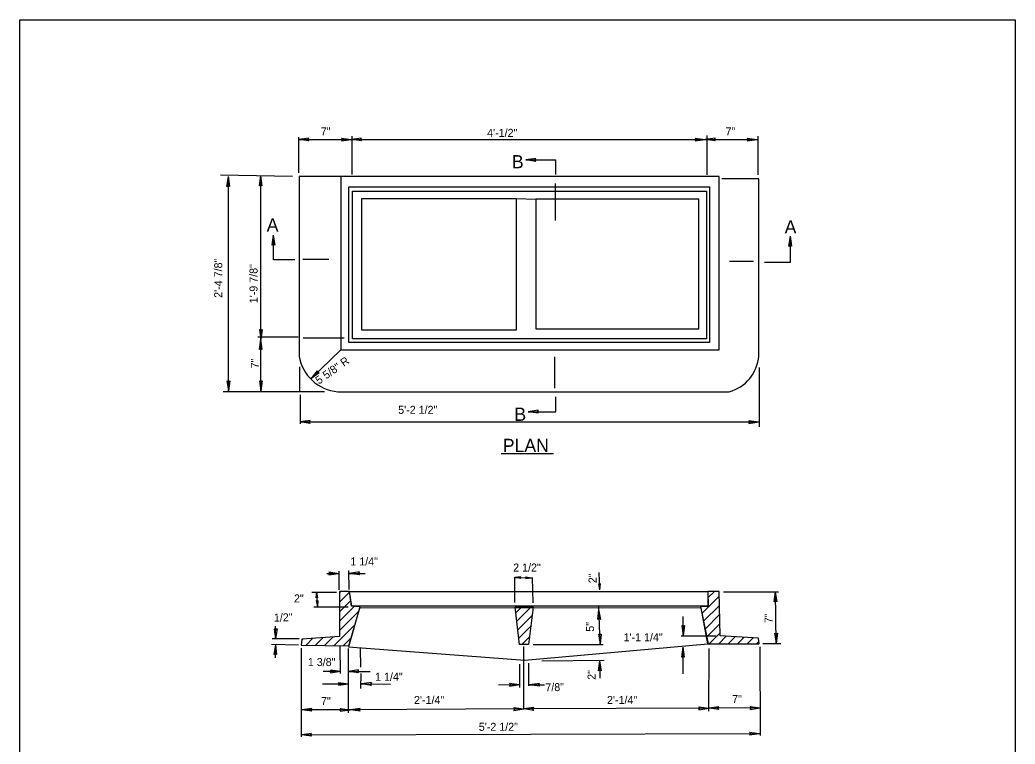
# Model space of a CAD drawing. Extents: x 0.7 to 8.1, y 0.4 to 10.6.
# Drawn here: x 0.66 to 8.12, y 5.19 to 10.63 of the extents above; entities that cross this region are included whole.
import ezdxf

# ---------------------------------------------------------------- set-up
doc = ezdxf.new("R2010")
doc.units = 0
for name, color, linetype in [('DETL-DIMS', 7, 'Continuous'), ('DETL-LINE', 7, 'Continuous'), ('DETL-NOTE', 7, 'Continuous'), ('DETL-TITL', 7, 'Continuous')]:
    doc.layers.add(name, color=color, linetype=linetype)

msp = doc.modelspace()

# ---------------------------------------------------------------- linework, layer by layer
at = {"layer": 'DETL-DIMS'}
for p, q in [((2.7543, 9.478), (2.7543, 9.7472)), ((2.8293, 9.7399), (2.7543, 9.729)), ((2.7543, 9.729), (3.1505, 9.729)), ((2.8293, 9.718), (2.7543, 9.729)), ((2.8293, 9.7399), (2.8199, 9.729)), ((2.8293, 9.718), (2.8199, 9.729)), ((3.0755, 9.7399), (3.1505, 9.729)), ((3.0755, 9.7399), (3.0849, 9.729)), ((3.0755, 9.718), (3.1505, 9.729)), ((3.0755, 9.718), (3.0849, 9.729)), ((3.2255, 9.7399), (3.1505, 9.729)), ((3.1505, 9.729), (5.8026, 9.729)), ((3.2255, 9.718), (3.1505, 9.729)), ((3.1541, 9.4671), (3.1541, 9.7544)), ((3.2255, 9.7399), (3.2161, 9.729)), ((3.2255, 9.718), (3.2161, 9.729)), ((5.7276, 9.718), (5.8027, 9.729)), ((5.7276, 9.718), (5.737, 9.729)), ((5.7277, 9.7399), (5.8027, 9.729)), ((5.7277, 9.7399), (5.737, 9.729)), ((5.8026, 9.729), (6.1916, 9.729)), ((5.8777, 9.7399), (5.8027, 9.729)), ((5.8777, 9.718), (5.8027, 9.729)), ((5.8172, 9.4636), (5.8172, 9.7582)), ((5.8777, 9.7399), (5.8683, 9.729)), ((5.8777, 9.718), (5.8683, 9.729)), ((6.1166, 9.7399), (6.1916, 9.729)), ((6.1166, 9.7399), (6.126, 9.729)), ((6.1166, 9.718), (6.1916, 9.729)), ((6.1166, 9.718), (6.126, 9.729)), ((6.1989, 9.4636), (6.1989, 9.7546)), ((4.5327, 9.587), (4.4576, 9.576)), ((4.5326, 9.5651), (4.4576, 9.576)), ((4.5327, 9.587), (4.5232, 9.576)), ((4.5326, 9.5651), (4.5232, 9.576)), ((2.7086, 9.4507), (2.1675, 9.4602)), ((2.2162, 9.3776), (2.2271, 9.4526)), ((2.2271, 7.8427), (2.2271, 9.4526)), ((2.238, 9.3776), (2.2271, 9.4526)), ((2.4597, 9.3812), (2.4706, 9.4562)), ((2.4706, 8.2282), (2.4706, 9.4562)), ((2.4816, 9.3812), (2.4706, 9.4562)), ((2.2162, 9.3776), (2.2271, 9.3869)), ((2.238, 9.3776), (2.2271, 9.3869)), ((2.4597, 9.3812), (2.4706, 9.3906)), ((2.4816, 9.3812), (2.4706, 9.3906)), ((4.6758, 9.3979), (4.6758, 9.1207)), ((2.5547, 8.9369), (2.5657, 9.0119)), ((2.5766, 8.9368), (2.5657, 9.0119)), ((6.4297, 8.9281), (6.4407, 9.0031)), ((6.4516, 8.9281), (6.4407, 9.0031)), ((2.5547, 8.9369), (2.5657, 8.9463)), ((2.5766, 8.9368), (2.5657, 8.9463)), ((6.4297, 8.9281), (6.4407, 8.9375)), ((6.4516, 8.9281), (6.4407, 8.9375)), ((2.9813, 8.8275), (2.7842, 8.8275)), ((5.9837, 8.8169), (6.1633, 8.8169)), ((2.4597, 8.3033), (2.4706, 8.2282)), ((2.4597, 8.3033), (2.4706, 8.2938)), ((2.4816, 8.3032), (2.4706, 8.2282)), ((2.4816, 8.3032), (2.4706, 8.2938)), ((2.7505, 8.2464), (2.4488, 8.2464)), ((2.4597, 8.1532), (2.4706, 8.2282)), ((2.4706, 7.8427), (2.4706, 8.2282)), ((2.4816, 8.1532), (2.4706, 8.2282)), ((3.0959, 8.2391), (2.7869, 8.2391)), ((2.4597, 8.1532), (2.4706, 8.1626)), ((2.4816, 8.1532), (2.4706, 8.1626)), ((3.0702, 8.1505), (2.8461, 7.9346)), ((4.6751, 7.8641), (4.6751, 8.0976)), ((2.7614, 8.0246), (2.7614, 7.8427)), ((2.8925, 7.9945), (2.8461, 7.9346)), ((2.8925, 7.9945), (2.8933, 7.9801)), ((6.2089, 7.5736), (6.2089, 8.0173)), ((2.2162, 7.9177), (2.2271, 7.8427)), ((2.2162, 7.9177), (2.2271, 7.9083)), ((2.238, 7.9177), (2.2271, 7.8427)), ((2.238, 7.9177), (2.2271, 7.9083)), ((2.4597, 7.9177), (2.4706, 7.8427)), ((2.4597, 7.9177), (2.4706, 7.9083)), ((2.4816, 7.9177), (2.4706, 7.8427)), ((2.4816, 7.9177), (2.4706, 7.9083)), ((2.9077, 7.9787), (2.8461, 7.9346)), ((2.9077, 7.9787), (2.8933, 7.9801)), ((2.9468, 7.8354), (2.1871, 7.8354)), ((2.7651, 7.8136), (2.7651, 7.5954)), ((4.5502, 7.698), (4.4752, 7.687)), ((4.5502, 7.6761), (4.4752, 7.687)), ((4.5502, 7.698), (4.5408, 7.687)), ((4.5502, 7.6761), (4.5408, 7.687)), ((2.8393, 7.6209), (2.7643, 7.61)), ((2.8393, 7.6209), (2.8299, 7.61)), ((6.128, 7.6209), (6.203, 7.61)), ((6.128, 7.6209), (6.1374, 7.61)), ((2.7643, 7.61), (6.203, 7.61)), ((2.8393, 7.599), (2.7643, 7.61)), ((2.8393, 7.599), (2.8299, 7.61)), ((6.128, 7.599), (6.203, 7.61)), ((6.128, 7.599), (6.1374, 7.61)), ((3.1336, 6.3524), (3.1291, 6.4947)), ((2.9659, 6.4737), (3.0558, 6.4737)), ((2.9808, 6.4847), (3.0558, 6.4737)), ((2.9808, 6.4847), (2.9901, 6.4737)), ((2.9808, 6.4628), (3.0558, 6.4737)), ((2.9808, 6.4628), (2.9901, 6.4737)), ((3.0588, 6.3509), (3.0573, 6.4902)), ((3.2101, 6.4847), (3.1351, 6.4737)), ((3.1351, 6.4737), (3.2519, 6.4737)), ((3.2101, 6.4628), (3.1351, 6.4737)), ((3.2101, 6.4847), (3.2008, 6.4737)), ((3.2101, 6.4628), (3.2008, 6.4737)), ((4.3757, 6.2563), (4.3735, 6.4448)), ((4.4208, 6.4483), (4.3757, 6.4426)), ((4.3757, 6.4426), (4.4998, 6.4403)), ((4.4206, 6.4352), (4.3757, 6.4426)), ((4.4208, 6.4483), (4.4151, 6.4418)), ((4.4206, 6.4352), (4.4151, 6.4418)), ((4.4547, 6.4346), (4.4605, 6.441)), ((4.4547, 6.4346), (4.4998, 6.4403)), ((4.455, 6.4477), (4.4998, 6.4403)), ((4.455, 6.4477), (4.4605, 6.441)), ((4.5109, 6.2541), (4.5065, 6.4426)), ((5.0052, 6.4803), (5.0096, 6.3516)), ((5.0015, 6.3964), (5.0097, 6.3516)), ((5.0015, 6.3964), (5.0083, 6.391)), ((5.0147, 6.3968), (5.0083, 6.391)), ((5.0147, 6.3968), (5.0097, 6.3516)), ((2.8536, 6.3329), (3.0378, 6.3329)), ((2.8848, 6.2892), (2.8896, 6.3344)), ((2.8848, 6.2892), (2.8912, 6.2951)), ((2.8857, 6.2698), (2.8941, 6.225)), ((2.8857, 6.2698), (2.8924, 6.2644)), ((2.894, 6.225), (2.8896, 6.3344)), ((2.898, 6.2897), (2.8896, 6.3344)), ((2.898, 6.2897), (2.8912, 6.2951)), ((2.8988, 6.2702), (2.8924, 6.2644)), ((2.8988, 6.2702), (2.8941, 6.225)), ((5.9401, 6.3362), (6.3524, 6.3362)), ((6.3184, 6.261), (6.328, 6.3362)), ((6.3184, 6.261), (6.3292, 6.2706)), ((6.3347, 5.9503), (6.328, 6.3362)), ((6.3403, 6.2614), (6.328, 6.3362)), ((6.3403, 6.2614), (6.3292, 6.2706)), ((2.8671, 6.2235), (3.1246, 6.2235)), ((4.9968, 6.1277), (5.0052, 6.2031)), ((5.0141, 5.9436), (5.0044, 6.227)), ((5.0187, 6.1284), (5.0052, 6.2031)), ((4.9968, 6.1277), (5.0074, 6.1375)), ((5.0187, 6.1284), (5.0074, 6.1375)), ((5.6365, 6.008), (5.6365, 6.1499)), ((2.5701, 6.0583), (2.5798, 5.9831)), ((2.5701, 6.0583), (2.5809, 6.0488)), ((2.5798, 5.9831), (2.5814, 6.0786)), ((2.592, 6.0579), (2.5798, 5.9831)), ((2.592, 6.0579), (2.5809, 6.0488)), ((5.6255, 6.083), (5.6365, 6.008)), ((5.6255, 6.083), (5.6365, 6.0736)), ((5.6474, 6.083), (5.6365, 6.008)), ((5.6474, 6.083), (5.6365, 6.0736)), ((2.758, 5.9831), (2.5544, 5.9831)), ((5.0006, 6.0182), (5.0141, 5.9436)), ((5.0006, 6.0182), (5.0118, 6.0092)), ((5.0224, 6.0189), (5.0118, 6.0092)), ((5.0224, 6.0189), (5.0141, 5.9436)), ((5.621, 6.0058), (5.8803, 6.0058)), ((6.3224, 6.0252), (6.3347, 5.9503)), ((6.3224, 6.0252), (6.3335, 6.0159)), ((6.3443, 6.0255), (6.3335, 6.0159)), ((6.3443, 6.0255), (6.3347, 5.9503)), ((2.5496, 5.9417), (2.7516, 5.9386)), ((2.5697, 5.8655), (2.583, 5.9402)), ((2.5798, 5.8415), (2.583, 5.9402)), ((2.5915, 5.8648), (2.583, 5.9402)), ((2.7751, 5.2482), (2.7751, 5.9134)), ((3.0666, 5.7221), (3.065, 5.9242)), ((3.1288, 5.4286), (3.1288, 5.9098)), ((3.2209, 5.7699), (3.2177, 5.9131)), ((4.5131, 5.9392), (5.0362, 5.9392)), ((5.6255, 5.8443), (5.6365, 5.9193)), ((5.6365, 5.7197), (5.6365, 5.9193)), ((5.6474, 5.8443), (5.6365, 5.9193)), ((5.8282, 5.439), (5.8305, 5.9091)), ((6.2162, 5.2588), (6.2126, 5.924)), ((6.2349, 5.9481), (6.3679, 5.9481)), ((2.5697, 5.8655), (2.5809, 5.8746)), ((2.5915, 5.8648), (2.5809, 5.8746)), ((4.577, 5.8173), (5.0447, 5.8217)), ((5.6255, 5.8443), (5.6365, 5.8537)), ((5.6474, 5.8443), (5.6365, 5.8537)), ((2.9916, 5.7506), (3.0666, 5.7396)), ((2.9916, 5.7506), (3.0009, 5.7396)), ((3.2036, 5.749), (3.1286, 5.738)), ((3.2036, 5.749), (3.1942, 5.738)), ((4.4127, 5.6177), (4.4127, 5.7939)), ((4.4791, 5.6307), (4.48, 5.7994)), ((5.0018, 5.7421), (5.0114, 5.8173)), ((5.0018, 5.7421), (5.0125, 5.7517)), ((5.0136, 5.6887), (5.0114, 5.8173)), ((5.0237, 5.7425), (5.0114, 5.8173)), ((5.0237, 5.7425), (5.0125, 5.7517)), ((2.9377, 5.7396), (3.0666, 5.7396)), ((2.9916, 5.7287), (3.0666, 5.7396)), ((2.9916, 5.7287), (3.0009, 5.7396)), ((3.1286, 5.738), (3.2893, 5.738)), ((3.2036, 5.7271), (3.1286, 5.738)), ((3.2036, 5.7271), (3.1942, 5.738)), ((3.2209, 5.6091), (3.2225, 5.7237)), ((2.933, 5.6441), (3.1286, 5.6457)), ((3.0535, 5.6561), (3.1286, 5.6457)), ((3.0535, 5.6561), (3.063, 5.6452)), ((3.0537, 5.6342), (3.1286, 5.6457)), ((3.0537, 5.6342), (3.063, 5.6452)), ((3.3007, 5.6545), (3.2256, 5.6442)), ((3.3006, 5.6327), (3.2256, 5.6442)), ((3.2256, 5.6441), (3.4436, 5.6426)), ((3.3007, 5.6545), (3.2913, 5.6437)), ((3.3006, 5.6327), (3.2913, 5.6437)), ((4.2533, 5.6371), (4.41, 5.639)), ((4.3348, 5.649), (4.41, 5.639)), ((4.3348, 5.649), (4.3443, 5.6382)), ((4.3351, 5.6271), (4.41, 5.639)), ((4.3351, 5.6271), (4.3443, 5.6382)), ((4.5588, 5.6484), (4.4837, 5.638)), ((4.4837, 5.638), (4.598, 5.6371)), ((4.5586, 5.6265), (4.4837, 5.638)), ((4.5588, 5.6484), (4.5493, 5.6375)), ((4.5586, 5.6265), (4.5493, 5.6375)), ((2.8537, 5.4608), (2.7787, 5.4498)), ((3.1394, 5.4498), (2.7787, 5.4498)), ((2.8537, 5.4389), (2.7787, 5.4498)), ((2.8537, 5.4608), (2.8443, 5.4498)), ((2.8537, 5.4389), (2.8443, 5.4498)), ((3.0644, 5.4608), (3.1394, 5.4498)), ((3.0644, 5.4608), (3.0738, 5.4498)), ((3.0644, 5.4389), (3.1394, 5.4498)), ((3.0644, 5.4389), (3.0738, 5.4498)), ((4.4432, 5.4569), (3.1288, 5.4498)), ((3.2143, 5.4612), (3.1394, 5.4498)), ((3.2144, 5.4393), (3.1394, 5.4498)), ((3.2143, 5.4612), (3.205, 5.4502)), ((3.2144, 5.4393), (3.205, 5.4502)), ((4.3681, 5.4674), (4.4432, 5.4569)), ((4.3681, 5.4674), (4.3775, 5.4565)), ((4.3682, 5.4455), (4.4432, 5.4569)), ((4.3682, 5.4455), (4.3775, 5.4565)), ((4.5181, 5.4681), (4.4432, 5.4569)), ((5.8283, 5.4625), (4.4432, 5.4569)), ((4.5182, 5.4463), (4.4432, 5.4569)), ((4.5181, 5.4681), (4.5088, 5.4572)), ((4.5182, 5.4463), (4.5088, 5.4572)), ((5.7532, 5.4731), (5.8283, 5.4624)), ((5.7532, 5.4731), (5.7627, 5.4622)), ((5.7533, 5.4512), (5.8283, 5.4624)), ((5.7533, 5.4512), (5.7627, 5.4622)), ((5.9032, 5.4737), (5.8283, 5.4624)), ((6.2126, 5.464), (5.8283, 5.4625)), ((5.9033, 5.4518), (5.8283, 5.4624)), ((5.9032, 5.4737), (5.8939, 5.4627)), ((5.9033, 5.4518), (5.8939, 5.4627)), ((6.1376, 5.4746), (6.2126, 5.464)), ((6.1376, 5.4746), (6.147, 5.4637)), ((6.1376, 5.4746), (6.2126, 5.464)), ((6.1376, 5.4746), (6.147, 5.4637)), ((6.1377, 5.4527), (6.2126, 5.464)), ((6.1377, 5.4527), (6.2126, 5.464)), ((6.1377, 5.4527), (6.147, 5.4637)), ((6.1377, 5.4527), (6.147, 5.4637)), ((2.8501, 5.2735), (2.7751, 5.2623)), ((2.7751, 5.2623), (6.2091, 5.2729)), ((2.8502, 5.2516), (2.7751, 5.2623)), ((2.8501, 5.2735), (2.8407, 5.2625)), ((2.8502, 5.2516), (2.8407, 5.2625)), ((6.1341, 5.2836), (6.2091, 5.2729)), ((6.1341, 5.2836), (6.1435, 5.2727)), ((6.1341, 5.2618), (6.2091, 5.2729)), ((6.1341, 5.2618), (6.1435, 5.2727))]:
    msp.add_line(p, q, dxfattribs=at)
for points in [[(4.4576, 9.576), (4.6785, 9.576), (4.6785, 9.4662)], [(2.7242, 8.8261), (2.5656, 8.8261), (2.5656, 9.0119)], [(6.2452, 8.8085), (6.4407, 8.8085), (6.4407, 9.0031)], [(4.4752, 7.687), (4.6818, 7.687), (4.6818, 7.798)]]:
    msp.add_lwpolyline(points, dxfattribs=at)
at = {"layer": 'DETL-LINE'}
for p, q in [((2.7565, 9.4522), (2.7565, 8.1044)), ((3.0702, 9.4504), (2.7565, 9.4522)), ((6.2027, 9.4337), (5.9259, 9.4337)), ((6.2027, 8.1044), (6.2027, 9.4337)), ((4.385, 9.286), (4.5327, 9.2814)), ((3.0471, 7.8367), (5.9813, 7.8367)), ((3.0604, 6.1862), (3.1441, 6.2699)), ((3.0606, 6.2571), (3.1354, 6.3319)), ((3.0608, 6.328), (3.0713, 6.3385)), ((5.7775, 6.1735), (5.9075, 6.3035)), ((5.8227, 6.2895), (5.8723, 6.3391)), ((3.0601, 6.1152), (3.1709, 6.226)), ((4.3824, 6.1784), (4.4241, 6.2201)), ((4.3895, 6.1148), (4.4943, 6.2196)), ((5.7894, 6.1147), (5.9087, 6.234)), ((3.0599, 6.0443), (3.2056, 6.1899)), ((4.3966, 6.0512), (4.5039, 6.1585)), ((5.8013, 6.0559), (5.9099, 6.1645)), ((3.0177, 5.9313), (3.1768, 6.0905)), ((4.4038, 5.9877), (4.494, 6.0779)), ((5.8132, 5.9971), (5.9111, 6.095)), ((2.7774, 5.9739), (2.7849, 5.9814)), ((2.8092, 5.935), (2.861, 5.9868)), ((2.8787, 5.9338), (2.9371, 5.9922)), ((2.9482, 5.9326), (3.0132, 5.9976)), ((3.0872, 5.9301), (3.148, 5.991)), ((4.4283, 5.9415), (4.4841, 5.9973)), ((5.8324, 5.9456), (5.9123, 6.0255)), ((5.9031, 5.9456), (5.9596, 6.0021)), ((5.9739, 5.9456), (6.0264, 5.9982)), ((6.0446, 5.9456), (6.0933, 5.9943)), ((6.1153, 5.9456), (6.1601, 5.9905)), ((4.4432, 5.4565), (4.4422, 5.9248)), ((6.186, 5.9456), (6.2036, 5.9632))]:
    msp.add_line(p, q, dxfattribs=at)
for points in [[(3.0702, 8.1505), (5.9075, 8.1505), (5.9075, 9.4504), (3.0702, 9.4504)], [(3.1302, 9.3737), (5.8336, 9.3737), (5.8336, 8.2059), (3.1302, 8.2059)], [(3.1578, 9.3414), (5.8106, 9.3414), (5.8106, 8.2336), (3.1578, 8.2336)], [(4.385, 8.2982), (3.227, 8.2982), (3.227, 9.286), (4.385, 9.286)], [(4.5327, 8.3075), (5.7552, 8.3075), (5.7552, 9.2814), (4.5327, 9.2814)], [(3.0608, 6.3385), (3.0598, 6.0009), (2.7781, 5.9809), (2.7738, 5.9357), (3.1302, 5.9294), (3.2154, 6.2238), (3.1502, 6.227), (3.1344, 6.3385)], [(3.1344, 6.3385), (5.8227, 6.3391), (5.8229, 6.227), (3.1527, 6.227)], [(5.8236, 5.9456), (6.206, 5.9456), (6.2001, 5.9881), (5.9127, 6.0048), (5.9069, 6.3391), (5.8227, 6.3391), (5.8227, 6.2257), (5.7669, 6.2257)], [(3.2113, 6.2123), (3.1271, 5.9228), (4.4493, 5.8239), (5.8227, 5.9448), (5.7716, 6.216)], [(4.5114, 6.2195), (4.4772, 5.9415), (4.409, 5.9415), (4.3777, 6.2204)]]:
    msp.add_lwpolyline(points, close=True, dxfattribs=at)
for centre, radius, start, end in [((3.077, 8.1607), 0.3254, 189.97018, 264.7334), ((5.9063, 8.1241), 0.297, 284.61206, 356.19507)]:
    msp.add_arc(centre, radius, start, end, dxfattribs=at)
at = {"layer": 'DETL-NOTE'}
msp.add_lwpolyline([(0.6641, 10.6264), (8.125, 10.6264), (8.125, 0.375), (0.6641, 0.375)], close=True, dxfattribs=at)
at = {"layer": 'DETL-TITL'}
msp.add_line((4.2715, 7.3721), (4.6655, 7.3721), dxfattribs=at)

# ---------------------------------------------------------------- texts
at = {"layer": 'DETL-DIMS'}
msp.add_text('5 5/8" R', height=0.06, rotation=35.34876, dxfattribs=at).set_placement((2.9059, 7.8894))
at = {"layer": 'DETL-NOTE'}
for s, p in [('7"', (2.9196, 9.7592)), ('4\'-1/2"', (4.1668, 9.749)), ('7"', (5.9537, 9.7592)), ('5\'-2 1/2"', (3.4999, 7.6709)), ('1 1/4"', (3.1412, 6.5333)), ('2 1/2"', (4.3621, 6.4878)), ('1\'-1 1/4"', (5.1895, 5.9643)), ('1 3/8"', (2.8227, 5.7784)), ('1 1/4"', (3.327, 5.6684)), ('7"', (2.9213, 5.4863)), ('2\'-1/4"', (3.6186, 5.4939)), ('2\'-1/4"', (5.0654, 5.4939)), ('7"', (6.0038, 5.5015)), ('5\'-2 1/2"', (4.1043, 5.2928))]:
    msp.add_text(s, height=0.06, dxfattribs=at).set_placement(p)
for s, rotation, p in [('2\'-4 7/8"', 90, (2.1809, 8.5413)), ('1\'-9 7/8"', 90, (2.4456, 8.5006)), ('7"', 90, (2.4558, 8.0116)), ('2"', 90, (4.9873, 6.4002)), ('2"', 360, (2.7187, 6.2557)), ('1/2"', 1.46756, (2.5691, 6.1118)), ('7"', 90, (6.3068, 6.1005)), ('5"', 90, (4.9684, 6.036)), ('2"', 90, (4.9798, 5.6756)), ('7/8"', 1.46756, (4.604, 5.5883))]:
    msp.add_text(s, height=0.06, rotation=rotation, dxfattribs=at).set_placement(p)
at = {"layer": 'DETL-TITL'}
for s, p in [('B', (4.3522, 9.5131)), ('A', (2.5145, 9.0382)), ('A', (6.3973, 9.024)), ('B', (4.3712, 7.6182)), ('PLAN', (4.284, 7.3845))]:
    msp.add_text(s, height=0.099, dxfattribs=at).set_placement(p)

doc.saveas('drawing.dxf')
